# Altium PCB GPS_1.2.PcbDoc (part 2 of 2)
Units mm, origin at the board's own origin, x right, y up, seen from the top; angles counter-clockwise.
Board outline 48.01 x 70.36 mm, 4 copper layers (Top Layer, GND, VDD, Bottom Layer); 58 components, 49 nets, 268 pads, 156 vias.
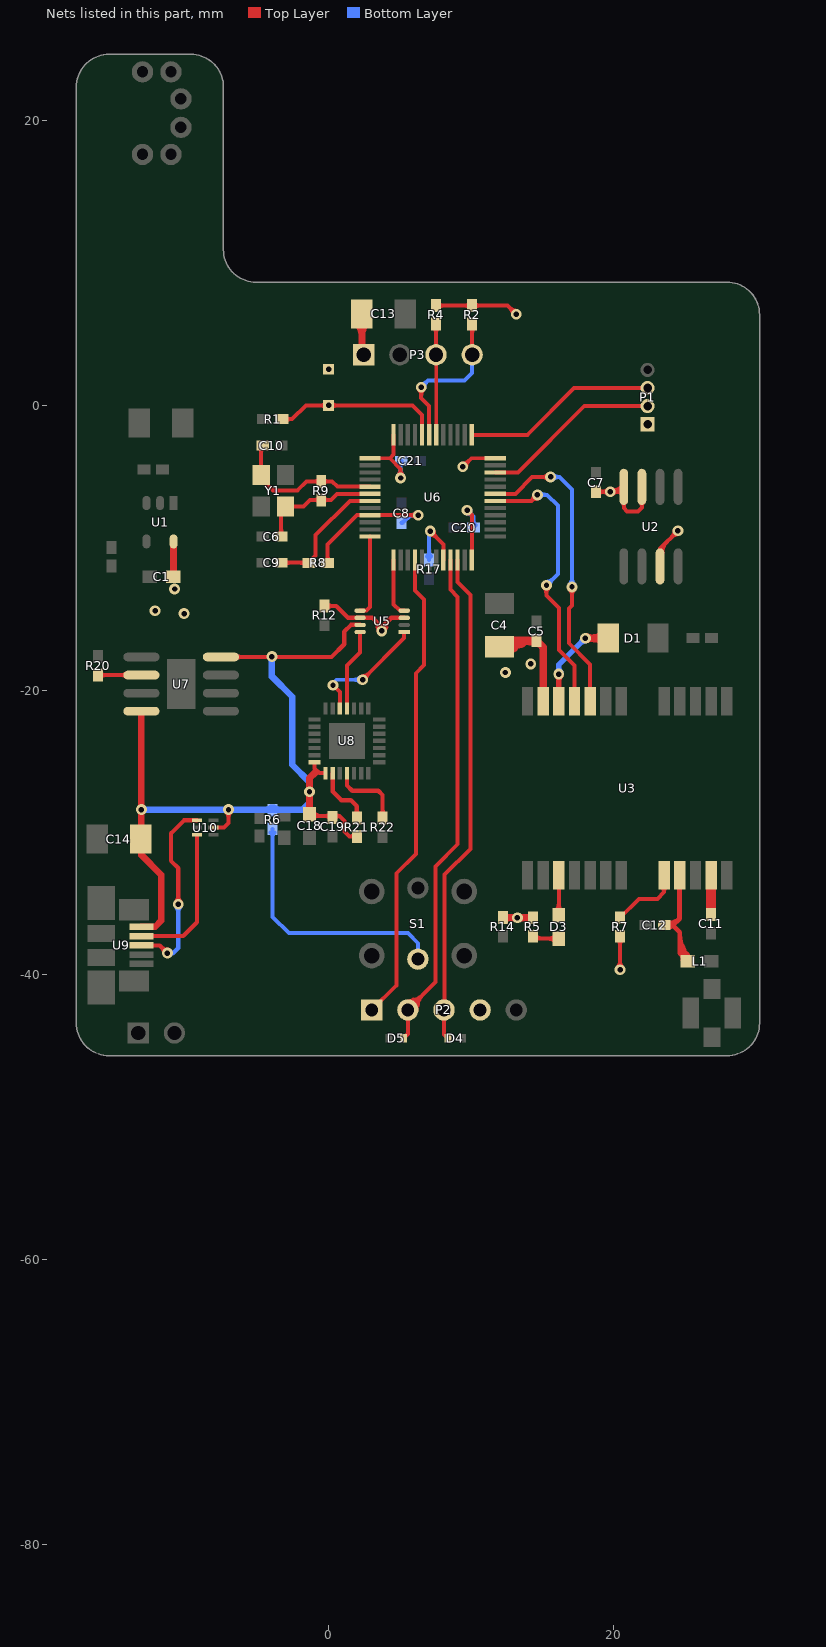
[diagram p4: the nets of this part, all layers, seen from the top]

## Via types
v1: diameter 0.762, hole 0.381, Top Layer to Bottom Layer, 156 vias

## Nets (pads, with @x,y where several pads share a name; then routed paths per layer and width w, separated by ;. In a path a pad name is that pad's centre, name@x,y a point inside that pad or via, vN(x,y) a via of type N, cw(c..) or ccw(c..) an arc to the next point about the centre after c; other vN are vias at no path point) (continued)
NetD1_2: D1.2 U3.22 | length 20.1
  Top Layer w0.381: U3.22@16.17,-20.803 v1(16.17,-18.882) ; v1(18.034,-16.358) D1.2@19.639,-16.358 ; 16.17,-19.342 cw(c16.63,-19.342) 16.305,-19.017 ccw(c16.63,-19.342) 16.17,-19.342 ; 16.17,-19.342 ccw(c15.71,-19.342) 16.035,-19.017 cw(c15.71,-19.342) 16.17,-19.342 ; v1@18.129,-16.523 cw(c18.472,-17.116) 18.649,-16.454 ; v1@18.129,-16.523 cw(c18.472,-17.116) 18.649,-16.454 ; v1@18.129,-16.523 cw(c18.472,-17.116) 18.649,-16.454 ; v1@18.129,-16.193 ccw(c18.472,-15.599) 18.649,-16.261 ; v1@18.129,-16.193 ccw(c18.472,-15.599) 18.649,-16.261 ; v1@18.129,-16.193 ccw(c18.472,-15.599) 18.649,-16.261 ; v1@18.289,-16.358 cw(c18.289,-17.708) 19.244,-16.753 ccw(c18.289,-17.708) v1@18.289,-16.358 ; v1@18.289,-16.358 ccw(c18.289,-15.007) 19.244,-15.962 cw(c18.289,-15.007) v1@18.289,-16.358 ; 18.494,-16.358 cw(c18.494,-15.898) 18.169,-16.223 ccw(c18.494,-15.898) 18.494,-16.358 ; 18.494,-16.358 ccw(c18.494,-16.818) 18.169,-16.492 cw(c18.494,-16.818) 18.494,-16.358
  Bottom Layer w0.381: v1(16.17,-18.882) 16.17,-18.222 v1(18.034,-16.358) ; 16.17,-18.422 cw(c15.71,-18.422) 16.035,-18.747 ccw(c15.71,-18.422) 16.17,-18.422 ; 16.17,-18.422 ccw(c16.63,-18.422) 16.305,-18.747 cw(c16.63,-18.422) 16.17,-18.422 ; 17.709,-16.683 cw(c18.034,-17.008) 18.034,-16.548 ccw(c18.034,-17.008) 17.709,-16.683 ; 17.709,-16.683 ccw(c17.384,-16.358) 17.843,-16.358 cw(c17.384,-16.358) 17.709,-16.683
NetD3_1: D3.1 R5.2 | length 5.4
  Top Layer w0.279: R5.2@14.351,-37.3 14.524,-37.473 D3.1@16.154,-37.473 ; 15.419,-37.473 cw(c15.419,-38.209) 15.939,-37.689 ccw(c15.419,-38.209) 15.419,-37.473 ; 15.419,-37.473 ccw(c15.419,-36.737) 15.939,-37.257 cw(c15.419,-36.737) 15.419,-37.473 ; R5.2@14.5,-37.251 ccw(c15.035,-36.715) 15.035,-37.473 cw(c15.035,-36.715) R5.2@14.5,-37.251
NetD3_2: D3.2 U3.3 | length 5.1
  Top Layer w0.279: D3.2@16.17,-35.806 U3.3@16.17,-33.003 ; D3.2@15.939,-35.543 ccw(c15.381,-34.985) 16.17,-34.985 cw(c15.381,-34.985) D3.2@15.939,-35.543 ; 16.17,-35.06 ccw(c16.853,-35.06) 16.37,-35.543 cw(c16.853,-35.06) 16.17,-35.06
NetR1_1: pad.1 R1.1 U6.44 | length 15.3
  Top Layer w0.279: R1.1@-3.272,-0.965 -2.565,-0.965 -1.6,0 5.893,0 6.558,-0.666 U6.44@6.558,-2.066 ; pad.1@-0.171,-0.171 ccw(c-0.583,-0.583) -0.583,0 ccw(c-0.583,0.583) pad.1@-0.171,0.171 ; pad.1@0.171,-0.171 cw(c0.583,-0.583) 0.583,0 cw(c0.583,0.583) pad.1@0.171,0.171 ; -2.664,-0.965 cw(c-2.664,-0.457) -3.023,-0.816 ccw(c-2.664,-0.457) -2.664,-0.965 ; -2.664,-0.965 ccw(c-2.664,-1.473) -3.023,-1.114 cw(c-2.664,-1.473) -2.664,-0.965
NetR6_2: R6.2 S1.6 | length 19.9
  Bottom Layer w0.279: R6.2@-3.937,-29.748 -3.937,-35.941 -2.794,-37.084 5.563,-37.084 6.271,-37.792 S1.6@6.271,-38.909 ; -3.937,-30.356 cw(c-3.429,-30.356) -3.788,-29.997 ccw(c-3.429,-30.356) -3.937,-30.356 ; -3.937,-30.356 ccw(c-4.445,-30.356) -4.086,-29.997 cw(c-4.445,-30.356) -3.937,-30.356
NetR7_1: R7.1 U3.8 | length 6.8
  Top Layer w0.279: R7.1@20.472,-36 21.801,-34.671 23.089,-34.671 23.57,-34.19 ; U3.8@23.57,-33.003 23.57,-34.19 ; 23.57,-34.19 cw(c24.102,-34.19) 23.745,-33.796 ccw(c24.102,-34.19) 23.57,-34.19 ; 23.57,-34.19 ccw(c23.038,-34.19) 23.395,-33.796 cw(c23.038,-34.19) 23.57,-34.19
NetR17_1: R17.1 U6.20 | length 8.3
  Top Layer w0.279: v1@7.1,-8.847 ccw(c7.483,-8.768) 7.382,-9.146 ; v1(7.137,-8.839) 8.058,-9.76 U6.20@8.058,-10.866 ; 7.549,-9.251 cw(c7.961,-8.839) 7.379,-8.839 ccw(c7.961,-8.839) 7.549,-9.251 ; 7.549,-9.251 ccw(c7.137,-9.663) 7.137,-9.08 cw(c7.137,-9.663) 7.549,-9.251
  Bottom Layer w0.279: R17.1@7.058,-10.866 7.058,-8.918 v1(7.137,-8.839) ; 7.058,-10.259 cw(c6.551,-10.259) 6.91,-10.618 ccw(c6.551,-10.259) 7.058,-10.259 ; 7.058,-10.259 ccw(c7.566,-10.259) 7.207,-10.618 cw(c7.566,-10.259) 7.058,-10.259
NetR20_2: R20.2 U7.2 | length 5.7
  Top Layer w0.305: R20.2@-16.201,-18.948 U7.2@-13.157,-18.948 ; -14.49,-18.948 cw(c-14.49,-19.316) -14.23,-19.056 ccw(c-14.49,-19.316) -14.49,-18.948 ; -14.49,-18.948 ccw(c-14.49,-18.58) -14.23,-18.841 cw(c-14.49,-18.58) -14.49,-18.948 ; R20.2@-16.065,-19.093 cw(c-15.717,-19.441) -15.717,-18.948 ccw(c-15.717,-19.441) R20.2@-16.065,-19.093 ; R20.2@-16.065,-18.813 ccw(c-15.739,-18.487) -15.739,-18.948 cw(c-15.739,-18.487) R20.2@-16.065,-18.813
NetR21_1: R21.1 U8.9 | length 5.7
  Top Layer w0.305: U8.9@0.283,-25.846 0.283,-27.13 0.889,-27.737 1.549,-27.737 1.981,-28.169 R21.1@1.981,-28.981 ; 1.981,-28.404 cw(c1.504,-28.404) 1.841,-28.742 ccw(c1.504,-28.404) 1.981,-28.404 ; 1.981,-28.404 ccw(c2.458,-28.404) 2.121,-28.742 cw(c2.458,-28.404) 1.981,-28.404
NetR22_1: R22.1 U8.11 | length 6.7
  Top Layer w0.305: U8.11@1.283,-25.846 1.283,-26.708 1.651,-27.076 3.48,-27.076 3.785,-27.381 R22.1@3.785,-28.981 ; 3.785,-28.404 cw(c3.308,-28.404) 3.645,-28.742 ccw(c3.308,-28.404) 3.785,-28.404 ; 3.785,-28.404 ccw(c4.262,-28.404) 3.924,-28.742 cw(c4.262,-28.404) 3.785,-28.404
NetU9_2: U9.2 U10.3 | length 10.4
  Top Layer w0.305: U9.2@-13.157,-37.287 -10.211,-37.287 -9.246,-36.322 U10.3@-9.246,-30.251
NetU9_3: U9.3 U10.1 | length 23
  Top Layer w0.305: U9.3@-13.157,-37.948 -11.862,-37.948 v1(-11.328,-38.481) ; v1@-11.557,-38.475 ccw(c-12.064,-38.462) -11.709,-38.1 ccw(c-11.347,-37.746) v1@-11.334,-38.252 ; v1@-11.33,-38.252 cw(c-11.335,-37.715) -11.719,-38.091 ; v1(-10.566,-35.052) -10.566,-32.512 -11.074,-32.004 -11.074,-30.074 -10.16,-29.159 U10.1@-9.246,-29.159 ; -11.719,-38.091 cw(c-12.109,-38.481) -11.557,-38.481 ccw(c-12.109,-38.481) -11.719,-38.091 ; -11.719,-38.091 ccw(c-11.328,-37.701) -11.328,-38.252 cw(c-11.328,-37.701) -11.719,-38.091 ; -11.719,-38.091 cw(c-12.094,-38.475) v1@-11.557,-38.479 ; -11.708,-38.102 ccw(c-11.337,-37.722) -11.331,-38.252 cw(c-11.337,-37.722) -11.708,-38.102 ; -11.708,-38.102 cw(c-12.087,-38.472) v1@-11.557,-38.478 ; -11.708,-38.102 cw(c-12.087,-38.472) v1@-11.557,-38.478 ; -10.566,-34.5 cw(c-11.118,-34.5) -10.728,-34.89 ccw(c-11.118,-34.5) -10.566,-34.5 ; -10.566,-34.5 ccw(c-10.015,-34.5) -10.405,-34.89 cw(c-10.015,-34.5) -10.566,-34.5
  Bottom Layer w0.305: v1(-11.328,-38.481) -10.922,-38.481 ; v1(-10.566,-35.052) -10.566,-38.125 -10.922,-38.481 ; -10.922,-38.481 cw(c-10.922,-38.234) -11.133,-38.362 ccw(c-10.922,-38.234) -10.922,-38.481 ; -10.922,-38.481 ccw(c-10.922,-38.728) -11.133,-38.6 cw(c-10.922,-38.728) -10.922,-38.481 ; -10.566,-35.604 cw(c-10.015,-35.604) -10.405,-35.214 ccw(c-10.015,-35.604) -10.566,-35.604 ; -10.566,-35.604 ccw(c-11.118,-35.604) -10.728,-35.214 cw(c-11.118,-35.604) -10.566,-35.604
NRST: C9.2 R8.1 U6.7 | length 12.1
  Top Layer w0.279: C9.2@-3.335,-11.057 -1.389,-11.057 R8.1@-1.372,-11.074 -1.372,-11.017 -0.914,-10.56 -0.914,-9.119 1.488,-6.716 U6.7@2.908,-6.716 ; -2.728,-11.057 cw(c-2.728,-10.549) -3.087,-10.908 ccw(c-2.728,-10.549) -2.728,-11.057 ; -2.728,-11.057 ccw(c-2.728,-11.565) -3.087,-11.206 cw(c-2.728,-11.565) -2.728,-11.057 ; -2.021,-11.057 cw(c-2.021,-11.624) -1.62,-11.223 ccw(c-2.021,-11.624) -2.021,-11.057 ; -1.937,-11.057 ccw(c-1.937,-10.609) -1.62,-10.926 cw(c-1.937,-10.609) -1.937,-11.057
OSC_IN: C10.2 R9.1 U6.5 Y1.3 | length 15.6
  Top Layer w0.279: C10.2@-4.635,-2.827 -4.743,-2.935 Y1.3@-4.743,-4.886 -4.743,-5.163 -3.915,-5.991 -2.206,-5.991 -1.557,-5.342 R9.1@-0.521,-5.342 0.237,-5.342 0.611,-5.716 U6.5@2.908,-5.716 ; -1.028,-5.342 cw(c-1.028,-5.85) -0.669,-5.491 ccw(c-1.028,-5.85) -1.028,-5.342 ; -1.028,-5.342 ccw(c-1.028,-4.834) -0.669,-5.193 cw(c-1.028,-4.834) -1.028,-5.342 ; -0.013,-5.342 cw(c-0.013,-4.834) -0.372,-5.193 ccw(c-0.013,-4.834) -0.013,-5.342 ; -0.013,-5.342 ccw(c-0.013,-5.85) -0.372,-5.491 cw(c-0.013,-5.85) -0.013,-5.342 ; C10.2@-4.884,-2.976 cw(c-5.225,-3.317) -4.743,-3.317 ccw(c-5.225,-3.317) C10.2@-4.884,-2.976 ; -4.743,-3.353 cw(c-4.209,-3.353) -4.587,-2.976 ccw(c-4.209,-3.353) -4.743,-3.353
OSC_OUT: C6.2 R9.2 U6.6 Y1.1 | length 13.3
  Top Layer w0.279: C6.2@-3.335,-9.228 -3.335,-7.409 Y1.1@-3.029,-7.103 -1.769,-7.103 -1.308,-6.642 R9.2@-0.521,-6.642 0.165,-6.642 0.591,-6.216 U6.6@2.908,-6.216 ; -3.335,-8.72 cw(c-3.843,-8.72) -3.484,-9.079 ccw(c-3.843,-8.72) -3.335,-8.72 ; -3.335,-8.72 ccw(c-2.828,-8.72) -3.187,-9.079 cw(c-2.828,-8.72) -3.335,-8.72 ; -1.028,-6.642 cw(c-1.028,-7.15) -0.669,-6.791 ccw(c-1.028,-7.15) -1.028,-6.642 ; -1.028,-6.642 ccw(c-1.028,-6.134) -0.669,-6.493 cw(c-1.028,-6.134) -1.028,-6.642 ; -0.013,-6.642 cw(c-0.013,-6.134) -0.372,-6.493 ccw(c-0.013,-6.134) -0.013,-6.642 ; -0.013,-6.642 ccw(c-0.013,-7.15) -0.372,-6.791 cw(c-0.013,-7.15) -0.013,-6.642
RF_IN: C11.2 U3.11 | length 2.8
  Top Layer w0.33: C11.2@26.87,-35.763 C11.2@26.873,-35.767
  Top Layer w0.711: C11.2@26.87,-35.763 U3.11@26.87,-33.003
RF_VCC: C12.2 L1.2 U3.9 | length 20.9
  Top Layer w0.33: C12.2@23.576,-36.525 24.181,-36.525 ; U3.9@24.67,-33.003 24.651,-33.022 24.651,-36.055 ; 24.732,-38.403 ccw(c25.462,-37.982) L1.2@25.244,-38.795 ; 24.829,-37.933 cw(c23.788,-38.534) L1.2@24.911,-38.965 ; 24.851,-38.608 cw(c24.412,-38.862) L1.2@24.902,-38.993 ; 25.175,-38.532 cw(c24.619,-38.853) L1.2@25.219,-39.083 ; L1.2@25.235,-39.065 24.67,-38.5 24.67,-37.014 24.181,-36.525 ; 24.122,-36.525 cw(c24.122,-36.079) 23.807,-36.394 ccw(c24.122,-36.079) 24.122,-36.525 ; 24.122,-36.525 ccw(c24.122,-36.972) 23.807,-36.656 cw(c24.122,-36.972) 24.122,-36.525 ; 24.181,-36.525 24.651,-36.055 ; 24.651,-36.055 cw(c23.909,-35.314) 23.711,-36.344 ccw(c23.909,-35.314) 24.651,-36.055 ; C12.2@23.648,-36.668 ccw(c23.767,-36.052) 24.211,-36.495 cw(c23.767,-36.052) C12.2@23.648,-36.668 ; 24.67,-37.977 ccw(c26.259,-37.977) 25.135,-39.101 cw(c26.259,-37.977) 24.67,-37.977 ; 24.67,-37.18 ccw(c27.056,-37.18) 25.369,-38.868 cw(c27.056,-37.18) 24.67,-37.18
RXD_G: U3.21 U6.30 | length 28
  Top Layer w0.279: U6.30@11.708,-6.716 14.239,-6.716 v1(14.668,-6.286) ; 14.362,-6.531 cw(c14.739,-6.632) v1@14.661,-6.249 ; 14.424,-6.593 ccw(c14.323,-6.216) v1@14.706,-6.294 ; v1@15.291,-12.636 15.291,-13.36 16.18,-14.249 16.18,-17.196 17.27,-18.286 U3.21@17.27,-20.803 ; 14.257,-6.698 cw(c14.668,-7.11) 14.668,-6.528 ccw(c14.668,-7.11) 14.257,-6.698 ; 14.257,-6.698 ccw(c13.845,-6.286) 14.427,-6.286 cw(c13.845,-6.286) 14.257,-6.698 ; v1@15.133,-12.807 cw(c14.752,-13.188) 15.291,-13.188 ccw(c14.752,-13.188) v1@15.133,-12.807 ; 15.291,-13.25 cw(c15.917,-13.25) 15.474,-12.807 ccw(c15.917,-13.25) 15.291,-13.25
  Bottom Layer w0.279: v1(14.668,-6.286) 15.354,-6.286 16.104,-7.036 16.104,-11.836 v1(15.303,-12.636) ; 15.251,-6.286 cw(c15.251,-5.704) 14.839,-6.116 ccw(c15.251,-5.704) 15.251,-6.286 ; 15.251,-6.286 ccw(c15.251,-6.869) 14.839,-6.457 cw(c15.251,-6.869) 15.251,-6.286 ; 15.715,-12.225 cw(c15.303,-11.813) 15.303,-12.395 ccw(c15.303,-11.813) 15.715,-12.225 ; 15.715,-12.225 ccw(c16.127,-12.636) 15.545,-12.636 cw(c16.127,-12.636) 15.715,-12.225
RXD_MCU: U5.4 U6.13 | length 4
  Top Layer w0.279: U6.13@4.558,-10.866 4.558,-13.982 5.002,-14.426 U5.4@5.309,-14.426
RXD_S: D4.2 P2.3 U6.22 | length 35.5
  Top Layer w0.279: D4.2@8.39,-44.475 8.103,-44.188 P2.3@8.103,-42.477 8.153,-42.426 8.153,-32.969 9.957,-31.166 9.957,-13.31 9.058,-12.411 U6.22@9.058,-10.866 ; 8.108,-44.194 ccw(c8.39,-43.912) 8.39,-44.31 cw(c8.39,-43.912) 8.108,-44.194
RXD_USB: U5.1 U8.26 | length 12.8
  Top Layer w0.279: v1(0.305,-19.66) 0.783,-20.138 U8.26@0.783,-21.299 ; v1@2.35,-19.271 cw(c2.733,-19.349) 2.632,-18.972 ; v1(2.388,-19.279) 5.309,-16.358 U5.1@5.309,-15.926 ; 2.8,-18.867 cw(c2.388,-18.455) 2.388,-19.037 ccw(c2.388,-18.455) 2.8,-18.867 ; 2.8,-18.867 ccw(c3.211,-19.279) 2.629,-19.279 cw(c3.211,-19.279) 2.8,-18.867
  Bottom Layer w0.279: v1(0.305,-19.66) 0.305,-19.533 0.559,-19.279 v1(2.388,-19.279) ; 1.805,-19.279 cw(c1.805,-19.861) 2.217,-19.449 ccw(c1.805,-19.861) 1.805,-19.279 ; 1.805,-19.279 ccw(c1.805,-18.696) 2.217,-19.108 cw(c1.805,-18.696) 1.805,-19.279
S_EN: P2.1 U6.16 | length 33.4
  Top Layer w0.279: P2.1@3.023,-42.477 4.75,-40.75 4.75,-32.893 6.121,-31.521 6.121,-18.821 6.706,-18.237 6.706,-13.64 6.058,-12.993 U6.16@6.058,-10.866
SCL: P3.3 R4.1 U6.42 | length 9.4
  Top Layer w0.279: P3.3@7.541,3.556 7.544,3.559 R4.1@7.544,5.715 ; U6.42@7.558,-2.066 P3.3@7.558,3.556 ; 7.544,5.107 cw(c8.052,5.107) 7.693,5.466 ccw(c8.052,5.107) 7.544,5.107 ; 7.544,5.107 ccw(c7.036,5.107) 7.395,5.466 cw(c7.036,5.107) 7.544,5.107
SDA: P3.4 R2.1 U6.43 | length 16.3
  Top Layer w0.279: v1(6.502,1.27) 6.502,0.508 7.058,-0.048 U6.43@7.058,-2.066 ; P3.4@10.081,3.556 10.084,3.559 R2.1@10.084,5.715 ; 6.502,0.687 cw(c7.085,0.687) 6.673,1.099 ccw(c7.085,0.687) 6.502,0.687 ; 6.502,0.687 ccw(c5.92,0.687) 6.332,1.099 cw(c5.92,0.687) 6.502,0.687 ; 10.084,5.107 cw(c10.592,5.107) 10.233,5.466 ccw(c10.592,5.107) 10.084,5.107 ; 10.084,5.107 ccw(c9.576,5.107) 9.935,5.466 cw(c9.576,5.107) 10.084,5.107
  Bottom Layer w0.279: v1(6.502,1.27) 6.985,1.753 9.55,1.753 10.081,2.283 P3.4@10.081,3.556 P3.4@10.081,3.573 ; 6.914,1.682 cw(c6.502,2.094) 6.502,1.511 ccw(c6.502,2.094) 6.914,1.682 ; 6.914,1.682 ccw(c7.326,1.27) 6.744,1.27 cw(c7.326,1.27) 6.914,1.682
SWCLK: P1.3 U6.37 | length 13.7
  Top Layer w0.279: U6.37@10.058,-2.066 13.961,-2.066 17.247,1.219 P1.3@22.403,1.219
SWDIO: P1.2 U6.34 | length 12.6
  Top Layer w0.279: U6.34@11.708,-4.716 13.292,-4.716 17.958,-0.051 P1.2@22.403,-0.051
TXD_G: U3.20 U6.31 | length 29.1
  Top Layer w0.279: U6.31@11.708,-6.216 13.113,-6.216 14.3,-5.029 v1(15.596,-5.029) ; v1(17.094,-12.751) 17.094,-14.072 16.891,-14.275 16.891,-16.713 18.37,-18.192 U3.20@18.37,-20.803 ; 15.013,-5.029 cw(c15.013,-5.612) 15.425,-5.2 ccw(c15.013,-5.612) 15.013,-5.029 ; 15.013,-5.029 ccw(c15.013,-4.447) 15.425,-4.859 cw(c15.013,-4.447) 15.013,-5.029 ; 17.094,-13.333 cw(c17.677,-13.333) 17.265,-12.921 ccw(c17.677,-13.333) 17.094,-13.333 ; 17.094,-13.333 ccw(c16.512,-13.333) 16.924,-12.921 cw(c16.512,-13.333) 17.094,-13.333
  Bottom Layer w0.279: v1(15.596,-5.029) 16.205,-5.029 17.094,-5.918 v1(17.094,-12.751) ; 16.178,-5.029 cw(c16.178,-4.447) 15.766,-4.859 ccw(c16.178,-4.447) 16.178,-5.029 ; 16.178,-5.029 ccw(c16.178,-5.612) 15.766,-5.2 cw(c16.178,-5.612) 16.178,-5.029 ; 17.094,-12.168 cw(c16.512,-12.168) 16.924,-12.58 ccw(c16.512,-12.168) 17.094,-12.168 ; 17.094,-12.168 ccw(c17.677,-12.168) 17.265,-12.58 cw(c17.677,-12.168) 17.094,-12.168
TXD_MCU: U5.5 U6.12 | length 5.8
  Top Layer w0.279: U5.5@2.209,-14.426 2.643,-14.426 2.908,-14.16 U6.12@2.908,-9.216
TXD_S: D5.2 P2.2 U6.21 | length 47.6
  Top Layer w0.279: D5.2@5.25,-44.475 5.563,-44.163 P2.2@5.563,-42.477 7.518,-40.521 7.518,-32.385 9.068,-30.836 9.068,-13.462 8.558,-12.953 U6.21@8.558,-10.866 ; P2.2@5.339,-42.431 cw(c6.204,-42.608) 5.975,-41.756 ; P2.2@5.552,-42.426 ccw(c5.33,-41.341) 6.4,-41.627 ; P2.2@5.608,-42.7 ccw(c5.431,-41.836) 6.283,-42.064 ; P2.2@5.613,-42.487 cw(c6.699,-42.709) 6.412,-41.639 ; 6.127,-41.912 cw(c5.563,-41.347) 5.563,-42.146 ccw(c5.563,-41.347) 6.127,-41.912 ; 6.127,-41.912 ccw(c6.692,-42.477) 5.894,-42.477 cw(c6.692,-42.477) 6.127,-41.912 ; 6.604,-41.435 cw(c5.563,-40.393) 5.563,-41.866 ccw(c5.563,-40.393) 6.604,-41.435 ; 6.604,-41.435 ccw(c7.646,-42.477) 6.173,-42.477 cw(c7.646,-42.477) 6.604,-41.435 ; D5.2@5.25,-44.31 ccw(c5.25,-43.912) 5.532,-44.194 cw(c5.25,-43.912) D5.2@5.25,-44.31
TXD_USB: U5.8 U8.25 | length 5.8
  Top Layer w0.279: U8.25@1.283,-21.299 1.283,-18.275 2.209,-17.349 U5.8@2.209,-15.926
USB-VBUS: C14.1 C18.1 C19.1 R6.1 R21.2 U5.7 U7.4 U7.8 U8.7 U8.8 U9.1 U10.5 | length 75.2
  Top Layer w0.279: U10.5@-8.096,-29.659 -7.358,-29.659 ; -7.358,-29.657 -7.036,-29.335 v1(-7.036,-28.397) ; C18.1@-1.346,-28.588 -1.079,-28.854 0.762,-28.854 ; U8.7@-0.991,-25.073 -0.991,-25.504 -0.649,-25.846 U8.8@-0.251,-25.846 ; R21.2@1.981,-30.281 1.452,-30.281 1.118,-29.947 1.118,-29.21 0.762,-28.854 ; -7.036,-28.98 cw(c-6.453,-28.98) -6.865,-28.568 ccw(c-6.453,-28.98) -7.036,-28.98 ; -7.036,-28.98 ccw(c-7.618,-28.98) -7.206,-28.568 cw(c-7.618,-28.98) -7.036,-28.98 ; 0.762,-28.854 cw(c0.762,-28.402) 0.433,-28.712 ccw(c0.762,-28.402) 0.762,-28.854 ; 0.762,-28.854 ccw(c0.762,-29.3) 0.434,-28.998 cw(c0.762,-29.3) 0.762,-28.854 ; 1.473,-30.281 cw(c1.473,-30.789) 1.832,-30.43 ccw(c1.473,-30.789) 1.473,-30.281 ; 1.473,-30.281 ccw(c1.473,-29.774) 1.832,-30.133 cw(c1.473,-29.774) 1.473,-30.281 ; C18.1@-1.131,-28.994 cw(c-0.794,-29.33) -0.794,-28.854 ccw(c-0.794,-29.33) C18.1@-1.131,-28.994 ; C18.1@-1.131,-28.563 ccw(c-0.426,-27.858) -0.426,-28.854 cw(c-0.426,-27.858) C18.1@-1.131,-28.563 ; -0.232,-28.854 cw(c-0.232,-29.368) 0.131,-29.005 ccw(c-0.232,-29.368) -0.232,-28.854 ; -0.224,-28.854 ccw(c-0.224,-28.352) 0.131,-28.707 cw(c-0.224,-28.352) -0.224,-28.854
  Top Layer w0.305: U7.8@-7.569,-17.678 0.203,-17.678 1.092,-16.789 1.092,-15.898 1.564,-15.426 U5.7@2.209,-15.426 ; -6.236,-17.678 cw(c-6.236,-17.31) -6.496,-17.571 ccw(c-6.236,-17.31) -6.236,-17.678 ; -6.236,-17.678 ccw(c-6.236,-18.046) -6.496,-17.786 cw(c-6.236,-18.046) -6.236,-17.678
  Top Layer w0.457: U9.1@-13.157,-36.627 -12.192,-36.627 -11.76,-36.195 -11.76,-32.995 -13.157,-31.598 v1(-13.157,-28.397) U7.4@-13.157,-21.488
  Top Layer w0.508: C18.1@-1.346,-28.588 v1(-1.346,-27.153) -1.346,-26.187 -0.927,-25.768 ; -1.346,-28.191 cw(c-1.806,-28.191) -1.481,-28.516 ccw(c-1.806,-28.191) -1.346,-28.191 ; -1.346,-28.191 ccw(c-0.886,-28.191) -1.211,-28.516 cw(c-0.886,-28.191) -1.346,-28.191
  Bottom Layer w0.457: v1(-13.157,-28.397) v1(-7.036,-28.397) -1.803,-28.397 -1.346,-27.94 v1(-1.346,-27.153) -1.346,-26.467 -2.565,-25.248 -2.565,-20.472 -3.988,-19.05 v1(-3.988,-17.653) ; -4.349,-28.397 ccw(c-4.349,-27.936) -4.023,-28.262 cw(c-4.349,-27.936) -4.349,-28.397 ; R6.1@-3.851,-28.262 ccw(c-3.525,-27.936) -3.525,-28.397 cw(c-3.525,-27.936) R6.1@-3.851,-28.262
VDD: C1.2 C4.1 C5.1 C7.1 C8.1 C13.2 C20.1 C21.1 P1.1 P2.4 P3.1 pad.0 R2.2 R4.2 R5.1 R7.2 R8.2 R12.1 R14.1 U1.5 U2.3 U2.7 U2.8 U3.23 U5.3 U5.6 U6.1 U6.9 U6.24 U6.36 U6.48 | length 132.1
  Top Layer w0.279: R8.2@-0.072,-11.074 -0.072,-9.774 1.986,-7.716 U6.9@2.908,-7.716 v1(6.294,-7.716) ; U6.1@2.908,-3.716 4.301,-3.716 ; U6.48@4.558,-2.066 4.558,-3.459 4.301,-3.716 ; v1(5.055,-5.105) 5.055,-4.47 4.301,-3.716 ; v1(9.423,-4.318) 10.025,-3.716 U6.36@11.708,-3.716 ; v1(9.728,-7.366) 10.058,-7.696 ; U6.24@10.058,-10.866 10.058,-7.696 ; C7.1@18.796,-6.071 v1(19.787,-6.071) ; 20.238,-5.955 cw(c20.522,-6.275) U2.8@20.679,-5.877 ; v1(20.472,-39.649) R7.2@20.472,-37.3 ; U2.8@20.739,-5.723 20.392,-6.071 ; U2.7@22.009,-5.723 22.009,-7.175 21.742,-7.442 20.955,-7.442 20.739,-7.226 20.739,-6.418 20.392,-6.071 ; U2.3@23.279,-11.311 23.279,-10.071 v1(24.536,-8.814) ; 24.292,-9.121 ccw(c24.191,-8.743) v1@24.574,-8.821 ; -0.072,-10.567 cw(c-0.579,-10.567) -0.22,-10.926 ccw(c-0.579,-10.567) -0.072,-10.567 ; -0.072,-10.567 ccw(c0.436,-10.567) 0.077,-10.926 cw(c0.436,-10.567) -0.072,-10.567 ; 5.055,-4.523 cw(c4.472,-4.523) 4.884,-4.935 ccw(c4.472,-4.523) 5.055,-4.523 ; 5.055,-4.523 ccw(c5.637,-4.523) 5.225,-4.935 cw(c5.637,-4.523) 5.055,-4.523 ; 5.711,-7.716 cw(c5.711,-8.299) 6.123,-7.887 ccw(c5.711,-8.299) 5.711,-7.716 ; 5.711,-7.716 ccw(c5.711,-7.134) 6.123,-7.546 cw(c5.711,-7.134) 5.711,-7.716 ; 9.835,-3.906 cw(c9.423,-3.494) 9.423,-4.077 ccw(c9.423,-3.494) 9.835,-3.906 ; 9.835,-3.906 ccw(c10.247,-4.318) 9.665,-4.318 cw(c10.247,-4.318) 9.835,-3.906 ; 10.058,-7.696 cw(c10.293,-7.462) 9.966,-7.406 ccw(c10.293,-7.462) 10.058,-7.696 ; 10.058,-7.696 ccw(c9.824,-7.93) 9.769,-7.604 cw(c9.824,-7.93) 10.058,-7.696 ; 19.204,-6.071 cw(c19.204,-6.653) 19.616,-6.241 ccw(c19.204,-6.653) 19.204,-6.071 ; 19.204,-6.071 ccw(c19.204,-5.488) 19.616,-5.9 cw(c19.204,-5.488) 19.204,-6.071 ; 19.304,-6.071 cw(c19.304,-5.563) 18.945,-5.922 ccw(c19.304,-5.563) 19.304,-6.071 ; 19.304,-6.071 ccw(c19.304,-6.578) 18.945,-6.219 cw(c19.304,-6.578) 19.304,-6.071 ; v1(19.787,-6.071) ccw(c19.787,-5.094) 20.601,-5.632 cw(c19.787,-5.094) v1(19.787,-6.071) ; v1(19.787,-6.071) 20.392,-6.071 ; v1@19.929,-5.876 ccw(c20.169,-5.545) 20.275,-5.94 ; v1@19.929,-5.876 ccw(c20.169,-5.545) 20.275,-5.94 ; v1@19.929,-5.876 ccw(c20.169,-5.545) 20.275,-5.94 ; v1@20.007,-6.169 cw(c20.38,-6.334) 20.275,-5.94 ; v1@20.007,-6.169 cw(c20.38,-6.334) 20.275,-5.94 ; v1@20.007,-6.169 cw(c20.38,-6.334) 20.275,-5.94 ; 20.369,-6.071 cw(c20.369,-5.488) 19.957,-5.9 ccw(c20.369,-5.488) 20.369,-6.071 ; 20.369,-6.071 ccw(c20.369,-6.653) 19.957,-6.241 cw(c20.369,-6.653) 20.369,-6.071 ; U2.8@20.457,-6.005 cw(c20.739,-6.287) 20.739,-5.888 ccw(c20.739,-6.287) U2.8@20.457,-6.005 ; U2.8@20.457,-6.005 ccw(c20.176,-5.723) 20.574,-5.723 cw(c20.176,-5.723) U2.8@20.457,-6.005 ; 20.472,-39.067 cw(c19.89,-39.067) 20.302,-39.479 ccw(c19.89,-39.067) 20.472,-39.067 ; 20.472,-39.067 ccw(c21.055,-39.067) 20.643,-39.479 cw(c21.055,-39.067) 20.472,-39.067 ; 20.472,-37.908 cw(c20.98,-37.908) 20.621,-37.549 ccw(c20.98,-37.908) 20.472,-37.908 ; 20.472,-37.908 ccw(c19.965,-37.908) 20.324,-37.549 cw(c19.965,-37.908) 20.472,-37.908 ; 20.739,-7.087 cw(c21.138,-7.087) 20.856,-6.805 ccw(c21.138,-7.087) 20.739,-7.087 ; 20.739,-7.087 ccw(c20.341,-7.087) 20.622,-6.805 cw(c20.341,-7.087) 20.739,-7.087 ; 22.009,-7.087 cw(c22.408,-7.087) 22.126,-6.805 ccw(c22.408,-7.087) 22.009,-7.087 ; 22.009,-7.087 ccw(c21.611,-7.087) 21.892,-6.805 cw(c21.611,-7.087) 22.009,-7.087 ; 24.124,-9.226 cw(c24.536,-9.638) 24.536,-9.055 ccw(c24.536,-9.638) 24.124,-9.226 ; 24.124,-9.226 ccw(c23.713,-8.814) 24.295,-8.814 cw(c23.713,-8.814) 24.124,-9.226 ; 20.306,-6.071 ccw(c20.306,-5.437) 20.835,-5.786 cw(c20.306,-5.437) 20.306,-6.071 ; U2.3@23.444,-10.346 cw(c24.506,-10.346) 23.755,-9.595 ccw(c24.506,-10.346) U2.3@23.444,-10.346
  Top Layer w0.305: R12.1@-0.279,-14.097 0.533,-14.097 1.362,-14.926 U5.6@2.209,-14.926 3.073,-14.926 v1@3.734,-15.586 ; 3.433,-15.578 ccw(c3.962,-15.437) v1@3.697,-15.916 ; v1(3.734,-15.85) v1@3.734,-15.586 ; v1@3.771,-15.916 ccw(c3.506,-15.437) 4.035,-15.578 ; U5.3@5.309,-14.926 4.394,-14.926 v1@3.734,-15.586 ; R4.2@7.544,7.015 R2.2@10.084,7.015 12.568,7.015 v1(13.183,6.401) ; v1@12.954,6.407 ccw(c12.447,6.419) 12.802,6.782 ccw(c13.164,7.136) v1@13.177,6.629 ; v1@13.181,6.629 cw(c13.176,7.166) 12.792,6.791 ; 0.198,-14.097 cw(c0.198,-13.62) -0.14,-13.957 ccw(c0.198,-13.62) 0.198,-14.097 ; 0.198,-14.097 ccw(c0.198,-14.574) -0.14,-14.237 cw(c0.198,-14.574) 0.198,-14.097 ; 8.021,7.015 cw(c8.021,7.492) 7.684,7.155 ccw(c8.021,7.492) 8.021,7.015 ; 8.021,7.015 ccw(c8.021,6.538) 7.684,6.875 cw(c8.021,6.538) 8.021,7.015 ; 9.607,7.015 cw(c9.607,6.538) 9.944,6.875 ccw(c9.607,6.538) 9.607,7.015 ; 9.607,7.015 ccw(c9.607,7.492) 9.944,7.155 cw(c9.607,7.492) 9.607,7.015 ; 10.561,7.015 cw(c10.561,7.492) 10.224,7.155 ccw(c10.561,7.492) 10.561,7.015 ; 10.561,7.015 ccw(c10.561,6.538) 10.224,6.875 cw(c10.561,6.538) 10.561,7.015 ; 12.792,6.791 cw(c12.402,6.401) 12.954,6.401 ccw(c12.402,6.401) 12.792,6.791 ; 12.792,6.791 ccw(c13.183,7.181) 13.183,6.629 cw(c13.183,7.181) 12.792,6.791 ; 12.792,6.791 cw(c12.417,6.407) v1@12.954,6.403 ; 12.803,6.78 ccw(c13.174,7.159) 13.18,6.629 cw(c13.174,7.159) 12.803,6.78 ; 12.803,6.78 cw(c12.424,6.41) v1@12.954,6.403 ; 12.803,6.78 cw(c12.424,6.41) v1@12.954,6.403 ; 3.157,-15.01 cw(c2.317,-15.85) 3.505,-15.85 ccw(c2.317,-15.85) 3.157,-15.01 ; v1@3.962,-15.85 cw(c5.15,-15.85) 4.31,-15.01 ccw(c5.15,-15.85) v1@3.962,-15.85
  Top Layer w0.508: C1.2@-10.897,-12.027 U1.5@-10.897,-9.558 ; C13.2@2.337,6.426 2.337,3.68 P3.1@2.461,3.556 ; C4.1@12.014,-16.967 12.471,-16.51 C5.1@14.605,-16.51 15.07,-16.975 U3.23@15.07,-20.803 ; R14.1@12.251,-36 v1(13.259,-36) R5.1@14.351,-36 ; C4.1@12.272,-16.976 ccw(c12.727,-16.515) 13.051,-17.076 ; C4.1@12.629,-16.614 ccw(c13.212,-16.023) 13.628,-16.742 ; 2.337,4.963 cw(c3.534,4.963) 2.688,5.809 ccw(c3.534,4.963) 2.337,4.963 ; 2.337,4.963 ccw(c1.139,4.963) 1.986,5.809 cw(c1.139,4.963) 2.337,4.963 ; C1.2@-11.044,-11.905 ccw(c-11.4,-11.549) -10.897,-11.549 cw(c-11.4,-11.549) C1.2@-11.044,-11.905 ; C4.1@12.272,-16.959 cw(c13.355,-18.042) 13.355,-16.51 ccw(c13.355,-18.042) C4.1@12.272,-16.959 ; C4.1@12.631,-17.318 cw(c14.581,-19.268) 14.581,-16.51 ccw(c14.581,-19.268) C4.1@12.631,-17.318 ; 14.115,-16.635 cw(c14.266,-17.197) 14.557,-16.693 ccw(c14.266,-17.197) 14.115,-16.635 ; C5.1@14.6,-16.706 cw(c14.574,-17.201) 15.07,-17.201 ccw(c14.574,-17.201) C5.1@14.6,-16.706 ; C5.1@14.605,-16.706 cw(c14.605,-17.179) 14.94,-16.845 ccw(c14.605,-17.179) C5.1@14.605,-16.706
  Bottom Layer w0.279: v1(5.055,-5.105) 5.055,-3.945 C21.1@5.105,-3.894 ; v1(9.728,-7.366) 10.185,-7.823 C20.1@10.185,-8.585 ; 5.055,-4.523 cw(c4.472,-4.523) 4.884,-4.935 ccw(c4.472,-4.523) 5.055,-4.523 ; 5.055,-4.523 ccw(c5.637,-4.523) 5.225,-4.935 cw(c5.637,-4.523) 5.055,-4.523 ; 10.14,-7.778 cw(c10.552,-7.366) 9.97,-7.366 ccw(c10.552,-7.366) 10.14,-7.778 ; 10.14,-7.778 ccw(c9.728,-8.19) 9.728,-7.607 cw(c9.728,-8.19) 10.14,-7.778 ; 10.185,-8.077 cw(c9.678,-8.077) 10.037,-8.436 ccw(c9.678,-8.077) 10.185,-8.077 ; 10.185,-8.077 ccw(c10.693,-8.077) 10.334,-8.436 cw(c10.693,-8.077) 10.185,-8.077 ; C21.1@4.857,-4.043 cw(c4.379,-4.521) 5.055,-4.521 ccw(c4.379,-4.521) C21.1@4.857,-4.043 ; 5.055,-4.283 cw(c5.394,-4.283) 5.154,-4.043 ccw(c5.394,-4.283) 5.055,-4.283
  Bottom Layer w0.305: C8.1@5.131,-8.238 5.206,-8.238 5.727,-7.716 v1(6.294,-7.716)
  other v1: 12.421,-18.771 14.199,-18.161 -10.16,-14.63 -12.192,-14.427 -10.82,-12.903
pads on no net: S1.0 S1.2 S1.4 S6.0 U3.1 U3.2 U3.4 U3.5 U3.6 U3.14 U3.15 U3.16 U3.17 U3.18 U3.19 U6.2 U6.3 U6.4 U6.10 U6.11 U6.14 U6.15 U6.18 U6.19 U6.32 U6.38 U6.39 U6.40 U6.41 U6.45 U6.46 U8.1 U8.2 U8.10 U8.12 U8.13 U8.14 U8.15 U8.16 U8.17 U8.18 U8.19 U8.20 U8.21 U8.22 U8.23 U8.24 U8.27 U8.28 U9.4

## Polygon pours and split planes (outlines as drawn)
GND on Top Layer "Top Layer-No Net" (solid, remove dead copper, pour order 2): -18.11,24.968 -18.11,-46.025 30.607,-46.025 30.607,9.017 23.978,9.017 -4.953,9.017 -4.953,25.07
GND on Bottom Layer "Top Layer-No Net" (solid, remove dead copper, pour order 3): -18.11,24.968 -18.11,-46.025 30.607,-46.025 30.607,9.017 23.978,9.017 -4.953,9.017 -4.953,25.07
GND on GND (split plane): -9.503,24.146 -9.331,24.121 -9.161,24.078 -8.997,24.02 -8.839,23.945 -8.69,23.855 -8.55,23.752 -8.42,23.634 -8.303,23.505 -8.199,23.365 -8.11,23.215 -8.035,23.058 -7.976,22.893 -7.934,22.724 -7.908,22.552 -7.9,22.391 -7.902,22.377 -7.902,10.939 -7.901,10.934 -7.893,10.72 -7.867,10.502 -7.824,10.287 -7.765,10.075 -7.689,9.869 -7.597,9.67 -7.49,9.478 -7.368,9.296 -7.232,9.123 -7.083,8.962 -6.921,8.813 -6.749,8.677 -6.566,8.555 -6.375,8.448 -6.175,8.356 -5.969,8.28 -5.758,8.221 -5.543,8.178 -5.325,8.152 -5.111,8.143 -5.105,8.143 27.985,8.143 27.999,8.144 28.159,8.136 28.332,8.111 28.501,8.068 28.665,8.01 28.823,7.935 28.972,7.845 29.112,7.742 29.242,7.624 29.359,7.495 29.463,7.355 29.553,7.205 29.627,7.048 29.686,6.883 29.728,6.714 29.754,6.542 29.762,6.381 29.76,6.367 29.76,-43.409 29.766,-43.463 29.76,-43.583 29.734,-43.755 29.692,-43.925 29.633,-44.089 29.559,-44.247 29.469,-44.396 29.365,-44.536 29.248,-44.666 29.118,-44.783 28.978,-44.887 28.829,-44.976 28.671,-45.051 28.507,-45.11 28.338,-45.152 28.165,-45.178 28.005,-45.186 27.991,-45.184 -15.443,-45.184 -15.457,-45.186 -15.617,-45.178 -15.79,-45.152 -15.959,-45.11 -16.123,-45.051 -16.281,-44.976 -16.431,-44.887 -16.571,-44.783 -16.7,-44.666 -16.817,-44.536 -16.921,-44.396 -17.011,-44.247 -17.085,-44.089 -17.144,-43.925 -17.187,-43.755 -17.212,-43.583 -17.22,-43.423 -17.219,-43.409 -17.219,22.377 -17.22,22.391 -17.212,22.552 -17.187,22.724 -17.144,22.893 -17.085,23.058 -17.011,23.215 -16.921,23.365 -16.817,23.505 -16.7,23.634 -16.571,23.752 -16.431,23.855 -16.281,23.945 -16.123,24.02 -15.959,24.078 -15.79,24.121 -15.617,24.146 -15.457,24.154 -15.443,24.153 -9.677,24.153 -9.663,24.154
BAT on VDD (split plane): -2.999,-25.169 -8.179,-25.169 -8.218,-25.177 -8.252,-25.2 -8.275,-25.233 -8.282,-25.273 -8.282,-44.676 -15.443,-44.676 -15.457,-44.677 -15.585,-44.67 -15.726,-44.646 -15.862,-44.607 -15.994,-44.552 -16.119,-44.483 -16.235,-44.401 -16.341,-44.306 -16.436,-44.2 -16.518,-44.084 -16.587,-43.959 -16.641,-43.828 -16.681,-43.691 -16.705,-43.551 -16.712,-43.422 -16.711,-43.409 -16.711,-20.474 -2.999,-20.474
VDD on VDD (split plane): -15.443,23.645 -9.677,23.645 -9.664,23.646 -9.535,23.639 -9.395,23.615 -9.258,23.576 -9.127,23.521 -9.002,23.452 -8.886,23.37 -8.78,23.275 -8.685,23.169 -8.603,23.053 -8.534,22.928 -8.479,22.797 -8.44,22.66 -8.416,22.52 -8.409,22.391 -8.41,22.377 -8.41,10.939 -8.409,10.937 -8.401,10.704 -8.376,10.469 -8.334,10.237 -8.276,10.009 -8.201,9.785 -8.111,9.567 -8.005,9.356 -7.885,9.153 -7.75,8.959 -7.602,8.776 -7.442,8.603 -7.269,8.442 -7.085,8.294 -6.892,8.16 -6.689,8.039 -6.478,7.934 -6.26,7.844 -6.036,7.769 -5.808,7.711 -5.576,7.669 -5.341,7.644 -5.108,7.635 -5.105,7.635 27.985,7.635 27.998,7.636 28.127,7.629 28.267,7.605 28.404,7.566 28.536,7.511 28.66,7.442 28.776,7.36 28.882,7.265 28.977,7.159 29.06,7.043 29.129,6.918 29.183,6.787 29.222,6.65 29.246,6.51 29.254,6.381 29.253,6.367 29.253,-43.409 29.257,-43.471 29.252,-43.551 29.228,-43.691 29.189,-43.828 29.135,-43.959 29.066,-44.084 28.983,-44.2 28.888,-44.306 28.782,-44.401 28.666,-44.483 28.542,-44.552 28.41,-44.607 28.273,-44.646 28.133,-44.67 28.004,-44.677 27.991,-44.676 -8.075,-44.676 -8.075,-25.377 -2.896,-25.377 -2.856,-25.369 -2.822,-25.346 -2.8,-25.313 -2.792,-25.273 -2.792,-20.371 -2.8,-20.331 -2.822,-20.298 -2.856,-20.275 -2.896,-20.267 -16.711,-20.267 -16.711,22.377 -16.712,22.391 -16.705,22.52 -16.681,22.66 -16.641,22.797 -16.587,22.928 -16.518,23.053 -16.436,23.169 -16.341,23.275 -16.235,23.37 -16.119,23.452 -15.994,23.521 -15.862,23.576 -15.726,23.615 -15.585,23.639 -15.457,23.646

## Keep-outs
Keep-Out Layer:
  circle w0.254: c-14.729,4.591 r1.6
  circle w0.254: c27.271,4.591 r1.6
  circle w0.254: c-3.729,-42.409 r1.6
  circle w0.254: c-4.294,-14.072 r1.5
  lines w0.203: 30.271,-43.409 30.271,6.367 ccw(c27.985,6.367) 27.985,8.653 -5.105,8.653 cw(c-5.105,10.939) -7.391,10.939 -7.391,22.377 ccw(c-9.677,22.377) -9.677,24.663 -15.443,24.663 ccw(c-15.443,22.377) -17.729,22.377 -17.729,-43.409 ccw(c-15.443,-43.409) -15.443,-45.695 27.991,-45.695 ccw(c27.991,-43.409) 30.277,-43.409

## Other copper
Top Layer:
  rectangle net BAT: -5.715,-22.377 -3.785,-21.184
  rectangle net BAT: -8.839,-23.546 -5.563,-21.184
  rectangle net VDD: -12.649,-14.808 -9.906,-13.36
  rectangle net VDD: -11.43,-14.046 -10.389,-12.192
  rectangle net VDD: 11.963,-19.126 14.859,-16.713
Bottom Layer:
  rectangle net BAT: -8.738,-23.546 -3.988,-21.311
VDD (plane layer: these items are gaps in the copper):
  lines w0.203: -16.739,-20.371 -2.896,-20.371 -2.896,-25.273 -8.179,-25.273 -8.179,-45.771 -7.899,-45.771

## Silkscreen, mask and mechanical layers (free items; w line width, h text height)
Top Overlay:
  lines w0.203: -1.397,-32.614 -1.397,-31.471 ; 2.159,-31.217 2.667,-31.725 ; 22.682,-14.529 23.622,-14.529 ; 23.139,-14.834 23.139,-14.173 ; 26.137,-34.696 26.822,-34.696 26.822,-34.874
Bottom Overlay:
  lines w0.203: 32.156,-83.49 32.334,-83.49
